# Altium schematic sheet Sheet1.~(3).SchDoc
size A4; SheetNumber: 1; SheetTotal: 1
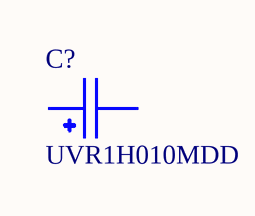
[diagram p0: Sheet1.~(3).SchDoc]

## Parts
C?  UVR1H010MDD  [CAPPRD200W50D550H1250]

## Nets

Not connected (* = marked no-connect by the designer): C? 1 2

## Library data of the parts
C? = UVR1H010MDD: 1 ÂµF 50 V Aluminum Electrolytic Capacitors Radial, Can - 2000 Hrs @ 85Â°C; MF: Nichicon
